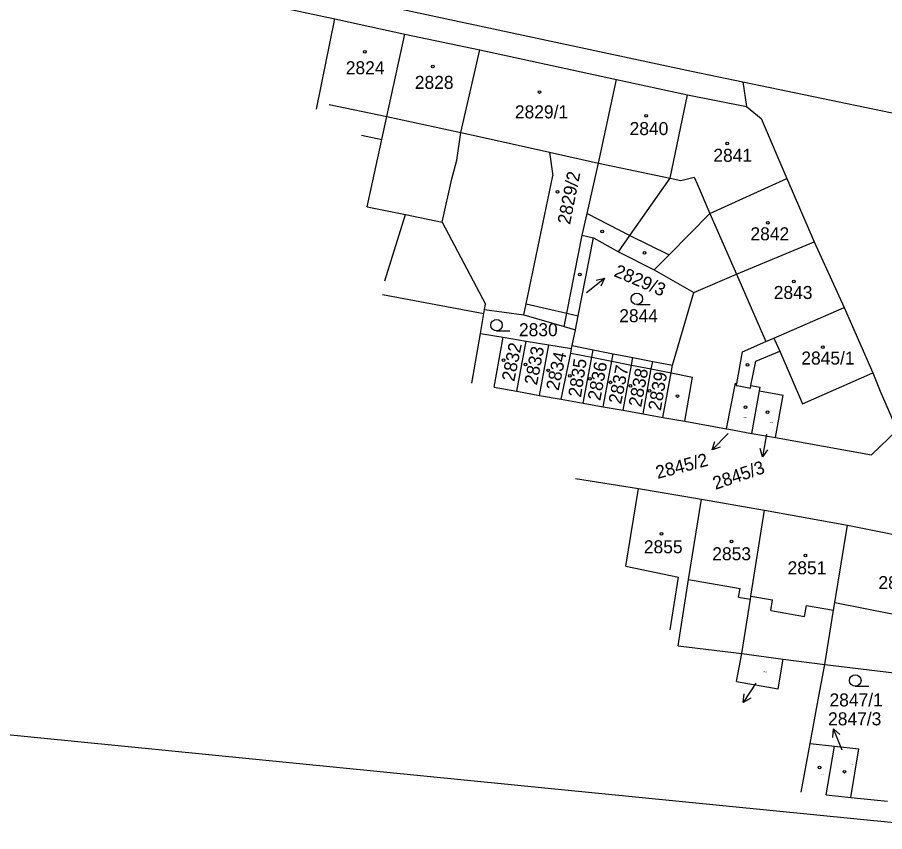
# Model space of a CAD drawing. Extents: x -735092 to -733385, y -1122435 to -1118992.
# Drawn here: x -734868.2 to -734755, y -1120128.4 to -1120022.1 of the extents above; entities that cross this region are included whole.
import ezdxf

# ---------------------------------------------------------------- set-up
doc = ezdxf.new("R2010")
doc.units = 0
for name, color, linetype in [('Vrstva 1', 7, 'Continuous'), ('Vrstva 16', 7, 'Continuous'), ('Vrstva 18', 7, 'Continuous'), ('Vrstva 19', 7, 'Continuous'), ('Vrstva 25', 7, 'Continuous'), ('Vrstva 4', 7, 'Continuous')]:
    doc.layers.add(name, color=color, linetype=linetype)

msp = doc.modelspace()

# ---------------------------------------------------------------- linework, layer by layer
at = {"layer": 'Vrstva 1'}
for points in [[(-734864.09, -1120011.11), (-734780.25, -1120029.09)], [(-734836.42, -1120020.21), (-734826.79, -1120022.25)], [(-734829.18, -1120034.04), (-734826.79, -1120022.25)], [(-734826.79, -1120022.25), (-734817.68, -1120024.26)], [(-734820.01, -1120035.01), (-734817.68, -1120024.26)], [(-734817.68, -1120024.26), (-734807.87, -1120026.29)], [(-734810.35, -1120037.1), (-734807.87, -1120026.29)], [(-734807.87, -1120026.29), (-734790.02, -1120030.17)], [(-734780.25, -1120029.09), (-734773.55, -1120030.48)], [(-734792.4, -1120041.08), (-734790.02, -1120030.17)], [(-734790.02, -1120030.17), (-734780.78, -1120032.17)], [(-734773.55, -1120030.48), (-734745.06, -1120036.39)], [(-734773.55, -1120030.48), (-734773.07, -1120033.71)], [(-734783.05, -1120043.05), (-734780.78, -1120032.17)], [(-734780.78, -1120032.17), (-734773.07, -1120033.71)], [(-734773.07, -1120033.71), (-734771.15, -1120035.26)], [(-734820.66, -1120038), (-734820.01, -1120035.01)], [(-734771.15, -1120035.26), (-734767.8, -1120043.12)], [(-734810.89, -1120040.71), (-734810.35, -1120037.1)], [(-734822.57, -1120046.81), (-734820.66, -1120038)], [(-734798.8, -1120039.66), (-734792.4, -1120041.08)], [(-734798.8, -1120039.66), (-734798.35, -1120042.74)], [(-734811.51, -1120043.15), (-734810.89, -1120040.71)], [(-734793.88, -1120047.66), (-734792.4, -1120041.08)], [(-734812.8, -1120048.79), (-734811.51, -1120043.15)], [(-734801.83, -1120059.46), (-734798.35, -1120042.74)], [(-734788.29, -1120050.56), (-734783.05, -1120043.05)], [(-734777.84, -1120047.65), (-734767.8, -1120043.12)], [(-734767.8, -1120043.12), (-734764.25, -1120051.36)], [(-734822.57, -1120046.81), (-734817.58, -1120047.82)], [(-734820.26, -1120056.46), (-734817.58, -1120047.82)], [(-734817.58, -1120047.82), (-734812.8, -1120048.79)], [(-734794.52, -1120050.5), (-734793.88, -1120047.66)], [(-734783.18, -1120053.07), (-734777.84, -1120047.65)], [(-734812.8, -1120048.79), (-734807.14, -1120059.51)], [(-734796.54, -1120060.68), (-734794.52, -1120050.5)], [(-734795.05, -1120061.02), (-734793.03, -1120050.84)], [(-734794.52, -1120050.5), (-734793.03, -1120050.84)], [(-734793.03, -1120050.84), (-734789.76, -1120052.68)], [(-734789.76, -1120052.68), (-734788.29, -1120050.56)], [(-734774.4, -1120055.58), (-734764.25, -1120051.36)], [(-734764.25, -1120051.36), (-734760.34, -1120059.94)], [(-734789.76, -1120052.68), (-734785.12, -1120055.04)], [(-734785.12, -1120055.04), (-734783.18, -1120053.07)], [(-734785.12, -1120055.04), (-734779.96, -1120057.98)], [(-734779.96, -1120057.98), (-734774.4, -1120055.58)], [(-734782.73, -1120067.49), (-734779.96, -1120057.98)], [(-734807.35, -1120060.72), (-734807.25, -1120060.19)], [(-734807.25, -1120060.19), (-734807.14, -1120059.51)], [(-734807.25, -1120060.19), (-734802.13, -1120060.9)], [(-734802.13, -1120060.9), (-734801.83, -1120059.46)], [(-734769.51, -1120063.95), (-734760.34, -1120059.94)], [(-734760.34, -1120059.94), (-734756.59, -1120068.49)], [(-734807.8, -1120063.35), (-734807.35, -1120060.72)], [(-734802.13, -1120060.9), (-734796.89, -1120062.41)], [(-734796.89, -1120062.41), (-734796.54, -1120060.68)], [(-734795.41, -1120062.84), (-734795.05, -1120061.02)], [(-734796.89, -1120062.41), (-734795.41, -1120062.84)], [(-734808.93, -1120069.83), (-734807.8, -1120063.35)], [(-734807.8, -1120063.35), (-734804.82, -1120063.83)], [(-734795.83, -1120064.91), (-734795.41, -1120062.84)], [(-734805.99, -1120070.36), (-734804.82, -1120063.83)], [(-734804.82, -1120063.83), (-734801.85, -1120064.32)], [(-734803.04, -1120070.88), (-734801.85, -1120064.32)], [(-734801.85, -1120064.32), (-734798.88, -1120064.8)], [(-734800.1, -1120071.41), (-734798.88, -1120064.8)], [(-734798.88, -1120064.8), (-734795.9, -1120065.28)], [(-734773.58, -1120065.74), (-734770.53, -1120064.4)], [(-734770.53, -1120064.4), (-734769.51, -1120063.95)], [(-734797.25, -1120071.92), (-734796.02, -1120065.89)], [(-734796.02, -1120065.89), (-734795.9, -1120065.28)], [(-734795.9, -1120065.28), (-734795.83, -1120064.91)], [(-734795.83, -1120064.91), (-734793.07, -1120065.46)], [(-734793.26, -1120066.43), (-734793.07, -1120065.46)], [(-734793.07, -1120065.46), (-734790.48, -1120065.97)], [(-734790.67, -1120066.94), (-734790.48, -1120065.97)], [(-734790.48, -1120065.97), (-734787.89, -1120066.48)], [(-734774.35, -1120069.85), (-734773.58, -1120065.74)], [(-734794.41, -1120072.43), (-734793.26, -1120066.43)], [(-734791.8, -1120072.9), (-734790.67, -1120066.94)], [(-734788.08, -1120067.45), (-734787.89, -1120066.48)], [(-734787.89, -1120066.48), (-734785.31, -1120066.99)], [(-734785.5, -1120067.96), (-734785.31, -1120066.99)], [(-734785.31, -1120066.99), (-734782.73, -1120067.49)], [(-734789.18, -1120073.36), (-734788.08, -1120067.45)], [(-734786.58, -1120073.83), (-734785.5, -1120067.96)], [(-734782.92, -1120068.47), (-734782.73, -1120067.49)], [(-734783.98, -1120074.29), (-734782.92, -1120068.47)], [(-734756.59, -1120068.49), (-734755.61, -1120070.88)], [(-734805.99, -1120070.36), (-734803.04, -1120070.88)], [(-734775.69, -1120075.78), (-734774.51, -1120069.82)], [(-734774.51, -1120069.82), (-734774.35, -1120069.85)], [(-734774.41, -1120070.12), (-734774.35, -1120069.85)], [(-734774.41, -1120070.12), (-734774.29, -1120070.14)], [(-734774.29, -1120070.14), (-734772.56, -1120070.49)], [(-734772.56, -1120070.49), (-734772.5, -1120070.14)], [(-734772.5, -1120070.14), (-734771.29, -1120070.35)], [(-734771.37, -1120070.82), (-734771.29, -1120070.35)], [(-734803.04, -1120070.88), (-734800.1, -1120071.41)], [(-734800.1, -1120071.41), (-734797.25, -1120071.92)], [(-734772.36, -1120076.38), (-734771.37, -1120070.82)], [(-734771.37, -1120070.82), (-734768.3, -1120071.37)], [(-734769.29, -1120076.93), (-734768.3, -1120071.37)], [(-734755.61, -1120070.88), (-734753.42, -1120075.94)], [(-734797.25, -1120071.92), (-734794.41, -1120072.43)], [(-734794.41, -1120072.43), (-734791.8, -1120072.9)], [(-734791.8, -1120072.9), (-734789.18, -1120073.36)], [(-734789.18, -1120073.36), (-734786.58, -1120073.83)], [(-734786.58, -1120073.83), (-734783.98, -1120074.29)], [(-734783.98, -1120074.29), (-734781.14, -1120074.8)], [(-734781.14, -1120074.8), (-734775.69, -1120075.78)], [(-734775.69, -1120075.78), (-734775.36, -1120075.84)], [(-734775.36, -1120075.84), (-734772.36, -1120076.38)], [(-734756.74, -1120079.17), (-734753.42, -1120075.94)], [(-734772.36, -1120076.38), (-734769.29, -1120076.93)], [(-734769.29, -1120076.93), (-734756.74, -1120079.17)], [(-734795.41, -1120082.28), (-734787.16, -1120083.57)], [(-734788.81, -1120093.71), (-734787.16, -1120083.57)], [(-734787.16, -1120083.57), (-734778.96, -1120084.96)], [(-734780.63, -1120095.44), (-734778.96, -1120084.96)], [(-734778.96, -1120084.96), (-734770.72, -1120086.41)], [(-734772.5, -1120097.61), (-734770.72, -1120086.41)], [(-734770.72, -1120086.41), (-734759.88, -1120088.36)], [(-734761.53, -1120098.46), (-734759.88, -1120088.36)], [(-734759.88, -1120088.36), (-734748.62, -1120090.64)], [(-734782.01, -1120104.13), (-734780.63, -1120095.44)], [(-734772.56, -1120098.03), (-734772.5, -1120097.61)], [(-734773.69, -1120105.13), (-734772.56, -1120098.03)], [(-734761.7, -1120099.46), (-734761.53, -1120098.46)], [(-734762.86, -1120106.55), (-734761.7, -1120099.46)], [(-734782.01, -1120104.13), (-734773.69, -1120105.13)], [(-734978.31, -1120104.89), (-734741.96, -1120128.37)], [(-734774.36, -1120108.76), (-734773.69, -1120105.13)], [(-734773.69, -1120105.13), (-734768.28, -1120105.84)], [(-734768.92, -1120109.73), (-734768.28, -1120105.84)], [(-734768.28, -1120105.84), (-734762.86, -1120106.55)], [(-734763.62, -1120110.68), (-734762.86, -1120106.55)], [(-734762.86, -1120106.55), (-734753.79, -1120107.64)], [(-734774.36, -1120108.76), (-734768.92, -1120109.73)], [(-734764.76, -1120116.86), (-734763.62, -1120110.68)], [(-734765.93, -1120123.22), (-734764.76, -1120116.86)], [(-734764.76, -1120116.86), (-734761.58, -1120117.21)], [(-734762.69, -1120123.56), (-734761.58, -1120117.21)], [(-734761.58, -1120117.21), (-734758.4, -1120117.56)], [(-734759.45, -1120123.9), (-734758.4, -1120117.56)], [(-734762.69, -1120123.56), (-734759.45, -1120123.9)], [(-734759.45, -1120123.9), (-734754.69, -1120124.4)]]:
    msp.add_lwpolyline(points, dxfattribs=at)
at = {"layer": 'Vrstva 25'}
for points in [[(-734793.96, -1120057.99), (-734791.613, -1120056.123)], [(-734792.707, -1120056.354), (-734791.613, -1120056.123), (-734792.084, -1120057.137)], [(-734787.39, -1120059.56), (-734785.64, -1120059.56)], [(-734805.69, -1120063), (-734803.94, -1120063)], [(-734775.46, -1120076.38), (-734777.562, -1120078.519)], [(-734770.45, -1120076.48), (-734770.991, -1120079.43)], [(-734776.505, -1120078.156), (-734777.562, -1120078.519), (-734777.218, -1120077.456)], [(-734770.32, -1120078.537), (-734770.991, -1120079.43), (-734771.302, -1120078.356)], [(-734771.86, -1120108.99), (-734773.489, -1120111.508)], [(-734758.88, -1120109.38), (-734757.13, -1120109.38)], [(-734772.526, -1120110.94), (-734773.489, -1120111.508), (-734773.366, -1120110.397)], [(-734761.8, -1120116.076), (-734761.722, -1120114.961), (-734760.876, -1120115.692)], [(-734760.57, -1120117.73), (-734761.722, -1120114.961)]]:
    msp.add_lwpolyline(points, dxfattribs=at)
for centre, radius in [((-734822.88, -1120026.56), 0.175), ((-734814.01, -1120028.47), 0.175), ((-734800.1, -1120031.81), 0.174), ((-734786.16, -1120034.93), 0.175), ((-734775.58, -1120038.53), 0.174), ((-734797.74, -1120044.83), 0.175), ((-734770.29, -1120048.89), 0.175), ((-734791.91, -1120050.02), 0.175), ((-734786.37, -1120052.81), 0.175), ((-734794.81, -1120055.64), 0.174), ((-734766.91, -1120056.55), 0.174), ((-734787.39, -1120058.81), 0.75), ((-734805.69, -1120062.25), 0.75), ((-734763.11, -1120065.11), 0.175), ((-734804.8, -1120066.83), 0.174), ((-734801.91, -1120067.39), 0.175), ((-734798.96, -1120068.15), 0.175), ((-734772.94, -1120067.43), 0.175), ((-734796.13, -1120068.87), 0.175), ((-734793.53, -1120069.26), 0.175), ((-734790.83, -1120069.71), 0.175), ((-734788.23, -1120070.17), 0.175), ((-734785.73, -1120070.82), 0.175), ((-734782.08, -1120071.5), 0.174), ((-734773.19, -1120072.96), 0.175), ((-734770.33, -1120073.61), 0.174), ((-734784.16, -1120089.49), 0.175), ((-734775.03, -1120090.5), 0.175), ((-734765.39, -1120092.33), 0.175), ((-734758.88, -1120108.63), 0.75), ((-734763.55, -1120120), 0.175), ((-734760.28, -1120120.54), 0.175)]:
    msp.add_circle(centre, radius, dxfattribs=at)
at = {"layer": 'Vrstva 4'}
for points in [[(-734827.56, -1120033.45), (-734820.01, -1120035.01)], [(-734820.01, -1120035.01), (-734810.35, -1120037.1)], [(-734823.3, -1120037.43), (-734820.66, -1120038)], [(-734810.35, -1120037.1), (-734807.97, -1120037.63)], [(-734807.97, -1120037.63), (-734798.8, -1120039.66)], [(-734792.4, -1120041.08), (-734783.05, -1120043.05)], [(-734783.05, -1120043.05), (-734781.63, -1120043.35)], [(-734781.63, -1120043.35), (-734779.9, -1120042.93)], [(-734779.9, -1120042.93), (-734779.52, -1120043.79)], [(-734779.52, -1120043.79), (-734777.84, -1120047.65)], [(-734793.88, -1120047.66), (-734788.29, -1120050.56)], [(-734777.84, -1120047.65), (-734774.4, -1120055.58)], [(-734788.29, -1120050.56), (-734783.18, -1120053.07)], [(-734774.4, -1120055.58), (-734770.53, -1120064.4)], [(-734820.57, -1120058.24), (-734807.35, -1120060.72)], [(-734801.83, -1120059.46), (-734796.54, -1120060.68)], [(-734796.54, -1120060.68), (-734795.05, -1120061.02)], [(-734769.51, -1120063.95), (-734769.41, -1120064.1)], [(-734769.41, -1120064.1), (-734768.73, -1120065.66)], [(-734796.02, -1120065.89), (-734793.26, -1120066.43)], [(-734771.84, -1120066.96), (-734768.73, -1120065.66)], [(-734768.73, -1120065.66), (-734765.76, -1120072.52)], [(-734793.26, -1120066.43), (-734790.67, -1120066.94)], [(-734790.67, -1120066.94), (-734788.08, -1120067.45)], [(-734772.5, -1120070.14), (-734771.84, -1120066.96)], [(-734788.08, -1120067.45), (-734785.5, -1120067.96)], [(-734785.5, -1120067.96), (-734782.92, -1120068.47)], [(-734782.92, -1120068.47), (-734780.1, -1120069.02)], [(-734781.14, -1120074.8), (-734780.1, -1120069.02)], [(-734765.76, -1120072.52), (-734756.59, -1120068.49)], [(-734788.81, -1120093.71), (-734781.97, -1120095.16)], [(-734783.04, -1120102.01), (-734781.97, -1120095.16)], [(-734780.63, -1120095.44), (-734773.92, -1120096.61)], [(-734774.12, -1120097.76), (-734773.92, -1120096.61)], [(-734772.5, -1120097.61), (-734769.66, -1120098.1)], [(-734774.12, -1120097.76), (-734772.56, -1120098.03)], [(-734769.9, -1120099.5), (-734769.66, -1120098.1)], [(-734765.5, -1120100.27), (-734765.26, -1120098.85)], [(-734765.26, -1120098.85), (-734761.7, -1120099.46)], [(-734761.53, -1120098.46), (-734754.05, -1120099.92)], [(-734769.9, -1120099.5), (-734765.5, -1120100.27)]]:
    msp.add_lwpolyline(points, dxfattribs=at)

# ---------------------------------------------------------------- texts
at = {"layer": 'Vrstva 16'}
for s, rotation, p in [('2829/3', 337.00268, (-734790.488, -1120055.815)), ('2845/2', 14.70012, (-734784.676, -1120082.329)), ('2845/3', 18.90015, (-734777.129, -1120083.754))]:
    msp.add_text(s, height=1.7, rotation=rotation, dxfattribs=at).set_placement(p)
msp.add_text('2847/3', height=1.7, dxfattribs=at).set_placement((-734762.43, -1120114.49))
at = {"layer": 'Vrstva 18'}
for s, height, p in [('2844', 1.7, (-734789.68, -1120061.86)), ('2830', 1.7, (-734802.77, -1120063.69)), ('2852/2', 0.1, (-734770.86, -1120107.55)), ('2847/1', 1.7, (-734762.24, -1120112.02))]:
    msp.add_text(s, height=height, dxfattribs=at).set_placement(p)
at = {"layer": 'Vrstva 19'}
for s, height, p in [('2824', 1.7, (-734825.37, -1120029.49)), ('2828', 1.7, (-734816.36, -1120031.4)), ('2829/1', 1.7, (-734803.3, -1120035.25)), ('2840', 1.7, (-734788.33, -1120037.43)), ('2841', 1.7, (-734777.4, -1120040.92)), ('2842', 1.7, (-734772.56, -1120051.17)), ('2843', 1.7, (-734769.52, -1120058.83)), ('2829/3', 0.1, (-734795.34, -1120059.05)), ('2845/1', 1.7, (-734765.92, -1120067.39)), ('2845/2', 0.1, (-734773.46, -1120074.35)), ('2845/3', 0.1, (-734770.01, -1120075)), ('2855', 1.7, (-734786.47, -1120092.03)), ('2853', 1.7, (-734777.54, -1120092.94)), ('2851', 1.7, (-734767.71, -1120094.77)), ('2846', 1.7, (-734755.86, -1120096.7)), ('2847/3', 0.1, (-734759.49, -1120119.64)), ('2847/2', 0.1, (-734763.35, -1120120.95))]:
    msp.add_text(s, height=height, dxfattribs=at).set_placement(p)
for s, rotation, p in [('2829/2', 78.70063, (-734796.106, -1120049.185)), ('2832', 78.50062, (-734803.386, -1120069.685)), ('2833', 79.10063, (-734800.428, -1120070.156)), ('2834', 78.00062, (-734797.604, -1120070.873)), ('2835', 81.30065, (-734794.677, -1120071.743)), ('2836', 79.40063, (-734792.159, -1120072.177)), ('2837', 78.40062, (-734789.455, -1120072.634)), ('2838', 79.20063, (-734786.828, -1120073.027)), ('2839', 80.20064, (-734784.263, -1120073.489))]:
    msp.add_text(s, height=1.7, rotation=rotation, dxfattribs=at).set_placement(p)

doc.saveas('drawing.dxf')
